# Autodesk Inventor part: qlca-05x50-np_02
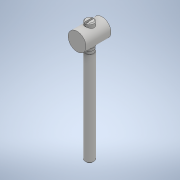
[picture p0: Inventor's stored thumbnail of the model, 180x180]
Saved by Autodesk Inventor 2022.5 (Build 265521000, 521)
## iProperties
Part Number: qlca-05x50-np_02
Material: 一般
Document SubType Name: Modeling
Designer: ImaoCorp
Density: 1 g/cm^3
Appearance: 既定
Author: ImaoCorp
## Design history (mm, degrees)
feature "qlca-05x50-np_02"
node "ソリッド1"
